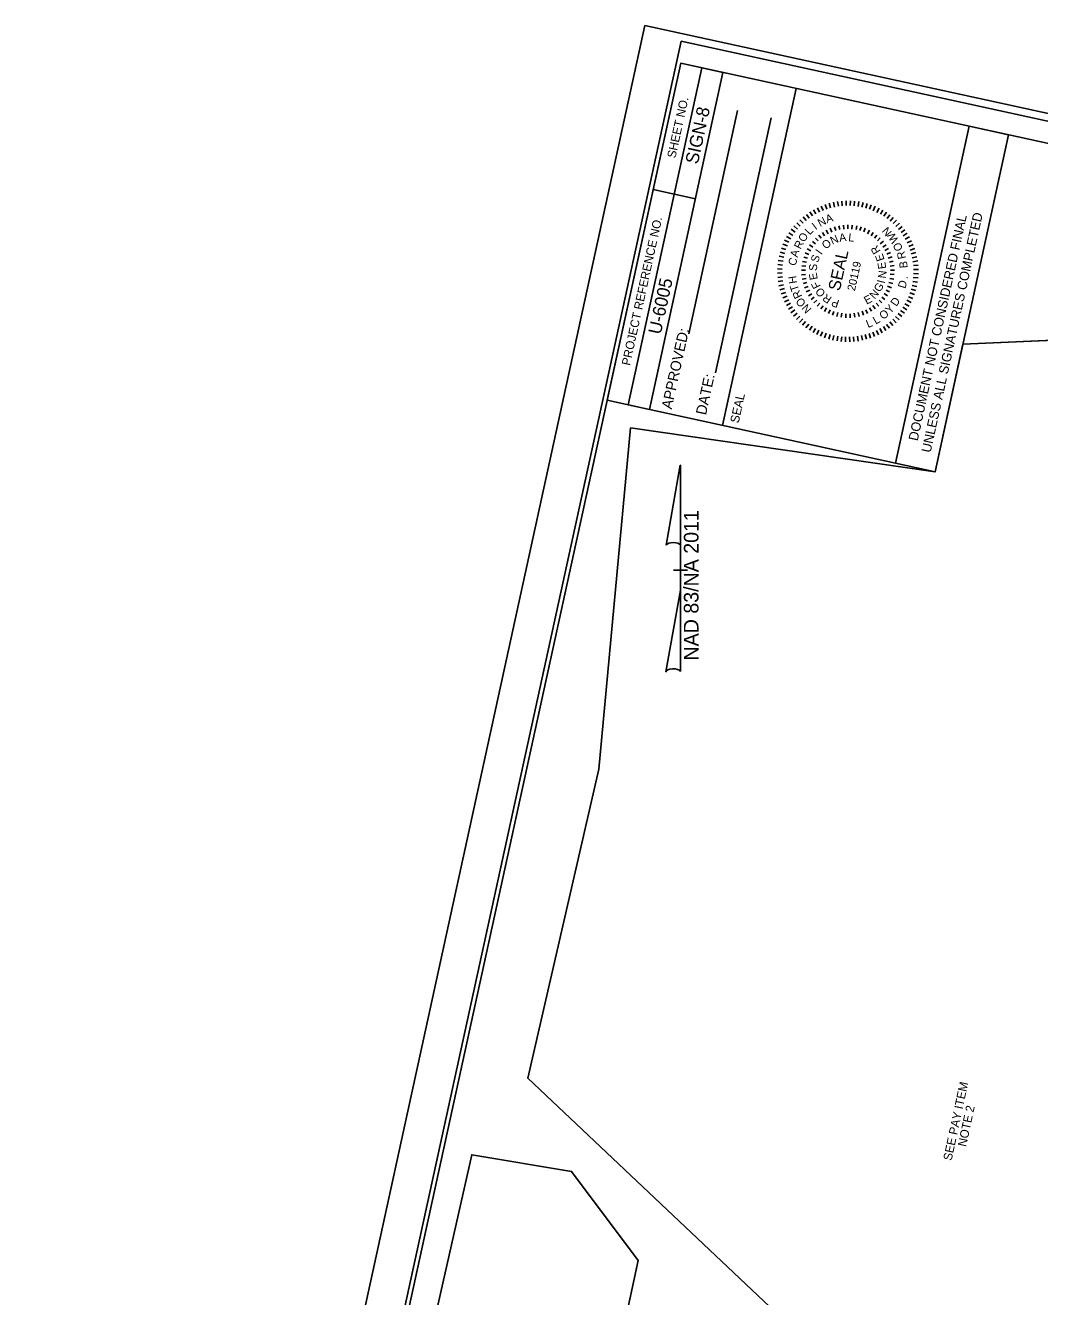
# Model space of a CAD drawing. Extents: x 1615829 to 1617263, y 900664 to 902544.
# Drawn here: x 1615829 to 1616417, y 901807 to 902544 of the extents above; entities that cross this region are included whole.
import ezdxf

# ---------------------------------------------------------------- set-up
doc = ezdxf.new("R2010")
doc.units = 0
for name, color, linetype in [('Default', 7, 'Continuous'), ('Old_Level_19', 7, 'Continuous'), ('Prop Conc 2ft 6in Curb and Gutter', 7, 'Continuous'), ('Prop Conc Drive Radius Type', 7, 'Continuous'), ('Prop Dimension', 7, 'Continuous'), ('Prop Dimension Text', 7, 'Continuous'), ('Prop PHM Concrete Structures Shape', 7, 'Continuous'), ('Prop Shade Medium', 7, 'Continuous'), ('Prop Superelevation  Arrow CELL', 7, 'Continuous'), ('Prop Superelevation Label', 7, 'Continuous'), ('Prop WCC CELL', 7, 'Continuous'), ('Scratch_Level_2', 7, 'Continuous')]:
    doc.layers.add(name, color=color, linetype=linetype)

msp = doc.modelspace()

# ---------------------------------------------------------------- linework, layer by layer
at = {"layer": 'Default'}
for p, q in [((1616283.7, 902435.68), (1616285.2, 902433.33)), ((1616285.81, 902436.95), (1616287.17, 902434.51)), ((1616288.01, 902438.08), (1616289.21, 902435.57)), ((1616290.26, 902439.09), (1616291.32, 902436.51)), ((1616292.57, 902439.95), (1616293.47, 902437.32)), ((1616294.94, 902440.68), (1616295.67, 902437.99)), ((1616297.34, 902441.25), (1616297.91, 902438.53)), ((1616299.77, 902441.69), (1616300.18, 902438.93)), ((1616302.22, 902441.98), (1616302.46, 902439.2)), ((1616304.69, 902442.12), (1616304.75, 902439.33)), ((1616307.15, 902442.11), (1616307.05, 902439.32)), ((1616309.62, 902441.94), (1616309.35, 902439.17)), ((1616312.06, 902441.64), (1616311.63, 902438.89)), ((1616314.49, 902441.18), (1616313.9, 902438.46)), ((1616316.89, 902440.58), (1616316.13, 902437.9)), ((1616319.24, 902439.83), (1616318.32, 902437.21)), ((1616321.55, 902438.95), (1616320.47, 902436.38)), ((1616323.79, 902437.93), (1616322.57, 902435.43)), ((1616325.98, 902436.77), (1616324.6, 902434.35)), ((1616328.08, 902435.49), (1616326.56, 902433.15)), ((1616276.1, 902429.4), (1616278.12, 902427.48)), ((1616277.85, 902431.14), (1616279.75, 902429.1)), ((1616279.71, 902432.77), (1616281.48, 902430.62)), ((1616281.66, 902434.28), (1616283.3, 902432.03)), ((1616303.1, 902428.06), (1616303.32, 902425.75)), ((1616305.69, 902428.2), (1616305.7, 902425.87)), ((1616308.29, 902428.07), (1616308.07, 902425.76)), ((1616330.11, 902434.07), (1616328.45, 902431.83)), ((1616332.05, 902432.54), (1616330.25, 902430.41)), ((1616333.89, 902430.89), (1616331.97, 902428.88)), ((1616335.62, 902429.14), (1616333.59, 902427.24)), ((1616270.22, 902421.49), (1616272.65, 902420.11)), ((1616271.51, 902423.6), (1616273.84, 902422.07)), ((1616272.92, 902425.62), (1616275.16, 902423.97)), ((1616274.45, 902427.56), (1616276.59, 902425.77)), ((1616286.89, 902420.5), (1616288.52, 902418.84)), ((1616288.83, 902422.23), (1616290.29, 902420.42)), ((1616290.94, 902423.76), (1616292.22, 902421.82)), ((1616293.18, 902425.09), (1616294.26, 902423.04)), ((1616295.54, 902426.19), (1616296.42, 902424.04)), ((1616297.99, 902427.06), (1616298.66, 902424.83)), ((1616300.52, 902427.69), (1616300.97, 902425.41)), ((1616310.87, 902427.7), (1616310.43, 902425.42)), ((1616313.4, 902427.08), (1616312.74, 902424.86)), ((1616314.91, 902424.1), (1616315.78, 902426.26)), ((1616318.22, 902425.13), (1616317.15, 902423.07)), ((1616320.47, 902423.81), (1616319.2, 902421.87)), ((1616322.57, 902422.29), (1616321.12, 902420.48)), ((1616324.52, 902420.57), (1616322.91, 902418.9)), ((1616337.25, 902427.29), (1616335.11, 902425.51)), ((1616338.77, 902425.33), (1616336.52, 902423.69)), ((1616340.16, 902423.3), (1616337.82, 902421.8)), ((1616341.43, 902421.18), (1616339, 902419.82)), ((1616267.16, 902414.76), (1616269.79, 902413.84)), ((1616268.04, 902417.06), (1616270.61, 902415.99)), ((1616269.06, 902419.31), (1616271.57, 902418.08)), ((1616282.17, 902414.31), (1616284.2, 902413.18)), ((1616283.54, 902416.52), (1616285.46, 902415.21)), ((1616285.12, 902418.59), (1616286.9, 902417.1)), ((1616326.3, 902418.66), (1616324.53, 902417.16)), ((1616327.88, 902416.6), (1616325.98, 902415.27)), ((1616329.26, 902414.39), (1616327.23, 902413.25)), ((1616342.57, 902418.99), (1616340.06, 902417.78)), ((1616343.57, 902416.73), (1616340.99, 902415.68)), ((1616344.44, 902414.42), (1616341.8, 902413.52)), ((1616265.36, 902407.58), (1616268.11, 902407.15)), ((1616265.81, 902410.01), (1616268.53, 902409.41)), ((1616266.41, 902412.41), (1616269.09, 902411.65)), ((1616279.42, 902407.02), (1616281.69, 902406.53)), ((1616281.69, 902406.53), (1616279.42, 902407.02)), ((1616280.11, 902409.54), (1616282.31, 902408.83)), ((1616281.02, 902411.97), (1616283.15, 902411.05)), ((1616330.42, 902412.06), (1616328.29, 902411.13)), ((1616331.35, 902409.62), (1616329.14, 902408.9)), ((1616332.03, 902407.11), (1616329.76, 902406.61)), ((1616345.16, 902412.06), (1616342.47, 902411.32)), ((1616345.74, 902409.66), (1616343.01, 902409.09)), ((1616346.18, 902407.23), (1616343.42, 902406.82)), ((1616264.88, 902400.2), (1616267.66, 902400.27)), ((1616264.89, 902402.67), (1616267.67, 902402.57)), ((1616265.05, 902405.13), (1616267.82, 902404.87)), ((1616278.81, 902401.86), (1616281.13, 902401.81)), ((1616278.87, 902399.26), (1616281.19, 902399.43)), ((1616278.99, 902404.46), (1616281.29, 902404.18)), ((1616332.48, 902404.54), (1616330.17, 902404.26)), ((1616332.61, 902399.35), (1616330.3, 902399.51)), ((1616332.67, 902401.95), (1616330.35, 902401.89)), ((1616346.46, 902404.78), (1616343.68, 902404.54)), ((1616346.59, 902399.84), (1616343.81, 902399.94)), ((1616346.6, 902402.31), (1616343.82, 902402.24)), ((1616265.01, 902397.73), (1616267.79, 902397.97)), ((1616265.3, 902395.28), (1616268.06, 902395.69)), ((1616265.74, 902392.85), (1616268.46, 902393.42)), ((1616266.31, 902390.45), (1616269, 902391.19)), ((1616279.19, 902396.68), (1616281.48, 902397.07)), ((1616279.76, 902394.13), (1616281.99, 902394.75)), ((1616280.56, 902391.66), (1616282.74, 902392.49)), ((1616330.94, 902391.75), (1616328.77, 902392.56)), ((1616331.75, 902394.22), (1616329.5, 902394.82)), ((1616332.3, 902396.76), (1616330.01, 902397.15)), ((1616345.66, 902392.5), (1616342.94, 902393.1)), ((1616346.12, 902394.93), (1616343.37, 902395.36)), ((1616346.43, 902397.38), (1616343.66, 902397.64)), ((1616267.04, 902388.09), (1616269.68, 902388.99)), ((1616267.91, 902385.78), (1616270.48, 902386.83)), ((1616268.91, 902383.53), (1616271.42, 902384.73)), ((1616281.61, 902389.27), (1616283.69, 902390.31)), ((1616282.88, 902387), (1616284.85, 902388.23)), ((1616284.36, 902384.86), (1616286.2, 902386.27)), ((1616286.04, 902382.87), (1616287.74, 902384.46)), ((1616325.49, 902382.94), (1616323.79, 902384.52)), ((1616327.17, 902384.94), (1616325.32, 902386.34)), ((1616328.65, 902387.08), (1616326.67, 902388.3)), ((1616327.82, 902390.37), (1616329.9, 902389.34)), ((1616342.41, 902383.2), (1616339.91, 902384.43)), ((1616343.43, 902385.45), (1616340.87, 902386.52)), ((1616344.32, 902387.75), (1616341.69, 902388.67)), ((1616345.06, 902390.11), (1616342.38, 902390.86)), ((1616270.05, 902381.33), (1616272.48, 902382.69)), ((1616271.32, 902379.21), (1616273.66, 902380.72)), ((1616272.71, 902377.18), (1616274.96, 902378.82)), ((1616274.23, 902375.22), (1616276.37, 902377)), ((1616287.9, 902381.06), (1616289.45, 902382.8)), ((1616289.94, 902379.43), (1616291.3, 902381.31)), ((1616292.12, 902378.01), (1616293.29, 902380.02)), ((1616294.43, 902376.8), (1616295.4, 902378.91)), ((1616296.84, 902375.83), (1616297.6, 902378.02)), ((1616299.33, 902375.09), (1616299.89, 902377.34)), ((1616301.89, 902374.59), (1616302.22, 902376.89)), ((1616304.48, 902374.35), (1616304.59, 902376.66)), ((1616307.09, 902374.35), (1616306.97, 902376.66)), ((1616309.68, 902374.6), (1616309.34, 902376.9)), ((1616312.23, 902375.11), (1616311.67, 902377.36)), ((1616314.72, 902375.86), (1616313.95, 902378.05)), ((1616317.13, 902376.84), (1616316.15, 902378.95)), ((1616319.43, 902378.06), (1616318.26, 902380.05)), ((1616321.61, 902379.48), (1616320.24, 902381.36)), ((1616323.63, 902381.12), (1616322.09, 902382.85)), ((1616337.03, 902374.95), (1616334.89, 902376.74)), ((1616338.55, 902376.89), (1616336.32, 902378.55)), ((1616339.97, 902378.91), (1616337.63, 902380.44)), ((1616341.26, 902381.02), (1616338.83, 902382.4)), ((1616275.85, 902373.37), (1616277.89, 902375.27)), ((1616277.59, 902371.62), (1616279.51, 902373.63)), ((1616279.43, 902369.97), (1616281.23, 902372.1)), ((1616281.37, 902368.44), (1616283.03, 902370.68)), ((1616283.39, 902367.03), (1616284.92, 902369.36)), ((1616327.78, 902366.83), (1616326.28, 902369.18)), ((1616329.82, 902368.23), (1616328.18, 902370.48)), ((1616331.77, 902369.74), (1616330, 902371.89)), ((1616333.62, 902371.37), (1616331.73, 902373.41)), ((1616335.38, 902373.11), (1616333.36, 902375.03)), ((1616285.5, 902365.74), (1616286.88, 902368.16)), ((1616287.69, 902364.58), (1616288.91, 902367.08)), ((1616289.93, 902363.56), (1616291.01, 902366.13)), ((1616292.24, 902362.68), (1616293.15, 902365.3)), ((1616294.59, 902361.93), (1616295.35, 902364.61)), ((1616296.98, 902361.33), (1616297.58, 902364.05)), ((1616299.41, 902360.87), (1616299.84, 902363.62)), ((1616301.86, 902360.57), (1616302.13, 902363.34)), ((1616304.32, 902360.4), (1616304.42, 902363.19)), ((1616306.79, 902360.39), (1616306.72, 902363.18)), ((1616309.26, 902360.53), (1616309.02, 902363.31)), ((1616311.71, 902360.82), (1616311.3, 902363.58)), ((1616314.14, 902361.26), (1616313.57, 902363.98)), ((1616316.54, 902361.83), (1616315.81, 902364.52)), ((1616318.9, 902362.56), (1616318, 902365.19)), ((1616321.22, 902363.42), (1616320.16, 902366)), ((1616323.47, 902364.43), (1616322.26, 902366.94)), ((1616325.66, 902365.57), (1616324.3, 902368))]:
    msp.add_line(p, q, dxfattribs=at)
at = {"layer": 'Prop Conc 2ft 6in Curb and Gutter'}
for p, q in [((1616200.34, 902242.5), (1616208.54, 902288.85)), ((1616208.59, 902288.85), (1616208.54, 902288.85)), ((1616208.59, 902288.85), (1616208.54, 902288.85)), ((1616208.59, 902288.85), (1616208.59, 902241.05)), ((1616208.59, 902216.25), (1616208.59, 902242.45)), ((1616208.59, 902241.05), (1616208.59, 902242.4)), ((1616204.59, 902227.85), (1616204.54, 902227.85)), ((1616208.14, 902227.85), (1616204.59, 902227.85)), ((1616204.64, 902227.85), (1616212.64, 902227.85)), ((1616208.59, 902216.25), (1616200.24, 902169)), ((1616208.64, 902169.2), (1616208.59, 902216.25))]:
    msp.add_line(p, q, dxfattribs=at)
for centre, start_param, end_param in [((1616204.47, 902242), 0.216388, 2.908219), ((1616204.47, 902168.83), 0.201328, 3.141593)]:
    msp.add_ellipse(centre, major_axis=(4.23, -0.03), ratio=0.461098, start_param=start_param, end_param=end_param, dxfattribs=at)
at = {"layer": 'Prop Conc Drive Radius Type'}
msp.add_lwpolyline([(1616850.42, 902379.94), (1617227.49, 902296.2), (1617121.36, 901790.43), (1617088.18, 901641.75), (1617042.44, 901522.26), (1617032.35, 901430.63), (1617021.35, 901334.38), (1616928.77, 900896.77), (1615902.83, 901120.28), (1615974.27, 901386.7), (1616087.67, 901888.92), (1616145.49, 901879.24), (1616184.12, 901827.49), (1616138.37, 901614.97), (1616150.59, 901618.07), (1616181.32, 901620.66), (1616299.19, 901764.2), (1616120.07, 901933.32), (1616161.35, 902112.51), (1616179.69, 902310.42), (1616356.27, 902284.95), (1616372.44, 902359.01)], close=True, dxfattribs=at)
at = {"layer": 'Prop Dimension'}
msp.add_lwpolyline([(1616333.32, 902289.96), (1616375.98, 902485.4), (1616398.93, 902480.39), (1616356.27, 902284.95)], close=True, dxfattribs=at)
at = {"layer": 'Prop Dimension Text'}
msp.add_line((1616372.44, 902359.01), (1616856.51, 902380.51), dxfattribs=at)
at = {"layer": 'Prop PHM Concrete Structures Shape'}
for p, q in [((1616178.38, 902323.78), (1616221.05, 902519.22)), ((1616190.6, 902321.11), (1616233.26, 902516.56)), ((1616190.6, 902321.11), (1616233.26, 902516.56)), ((1616192.84, 902448.61), (1616217.27, 902443.28))]:
    msp.add_line(p, q, dxfattribs=at)
for points in [[(1616208.79, 902521.9), (1615888.89, 901056.41), (1616914.73, 900832.48), (1617234.63, 902297.97)], [(1616166.12, 902326.45), (1616208.79, 902521.9), (1616233.26, 902516.56), (1616190.6, 902321.11)]]:
    msp.add_lwpolyline(points, close=True, dxfattribs=at)
at = {"layer": 'Prop Shade Medium'}
msp.add_lwpolyline([(1616187.99, 902543.84), (1615828.85, 900898.58), (1616903.54, 900663.99), (1617262.68, 902309.25)], close=True, dxfattribs=at)
at = {"layer": 'Prop Superelevation  Arrow CELL'}
for p, q in [((1616233.02, 902311.85), (1616275.68, 902507.3)), ((1616375.98, 902485.4), (1616333.32, 902289.96)), ((1616224.48, 902313.71), (1616178.38, 902323.78)), ((1616333.32, 902289.96), (1616224.48, 902313.71))]:
    msp.add_line(p, q, dxfattribs=at)
at = {"layer": 'Prop WCC CELL'}
for p, q in [((1616213.43, 902364.94), (1616241.71, 902494.5)), ((1616228.89, 902342.44), (1616261.16, 902490.26))]:
    msp.add_line(p, q, dxfattribs=at)
at = {"layer": 'Scratch_Level_2'}
msp.add_lwpolyline([(1616208.96, 902534.66), (1615853.55, 900906.5), (1616884.38, 900681.48), (1617239.79, 902309.64)], close=True, dxfattribs=at)

# ---------------------------------------------------------------- texts
at = {"layer": 'Default'}
for s, height, rotation, p in [('I', 4.64, 37.2123, (1616287.03, 902425.04)), ('N', 4.64, 27.91784, (1616289.67, 902426.85)), ('A', 4.64, 18.15031, (1616293.67, 902429.11)), ('O', 4.64, 59.92405, (1616280.57, 902417.8)), ('L', 4.64, 46.78777, (1616283.6, 902421.97)), ('N', 4.64, 24.09635, (1616296.7, 902416.6)), ('A', 4.64, 8.8001, (1616300.96, 902418.27)), ('L', 4.64, 353.50386, (1616305.77, 902418.76)), ('N', 4.64, 129.84026, (1616331.57, 902424.01)), ('W', 4.64, 120.95763, (1616335.3, 902419.21)), ('R', 4.64, 62.98087, (1616278.31, 902413.69)), ('I', 4.64, 54.68884, (1616290.34, 902410.51)), ('O', 4.64, 39.39259, (1616292.9, 902413.78)), ('R', 4.64, 122.1981, (1616324.86, 902412.97)), ('O', 4.64, 112.07501, (1616337.73, 902414.01)), ('C', 4.64, 74.99017, (1616275.41, 902404.1)), ('A', 4.64, 74.99017, (1616276.58, 902409.04)), ('S', 4.64, 69.98509, (1616288.3, 902405.9)), ('SEAL', 6.965, 77.63321, (1616301.02, 902389.51)), ('20119', 4.64, 77.63321, (1616309.77, 902389.54)), ('E', 4.64, 108.42701, (1616327.07, 902407.96)), ('E', 4.64, 98.44113, (1616327.99, 902402.89)), ('R', 4.64, 103.25239, (1616339.45, 902408.91)), ('B', 4.64, 94.24983, (1616340.36, 902403.22)), ('H', 4.64, 98.70086, (1616276.34, 902394.45)), ('E', 4.64, 100.57758, (1616288.31, 902396.7)), ('S', 4.64, 85.28133, (1616287.69, 902401.29)), ('N', 4.64, 83.04906, (1616327.74, 902396.93)), ('T', 4.64, 108.13281, (1616277.52, 902390.37)), ('F', 4.64, 115.87382, (1616290.08, 902392.51)), ('O', 4.64, 131.17007, (1616293.07, 902388.69)), ('G', 4.64, 57.32461, (1616324.28, 902388.8)), ('I', 4.64, 75.4194, (1616326.92, 902393.88)), ('D', 4.64, 73.72316, (1616339, 902390.95)), ('.', 4.64, 81.46551, (1616340.29, 902396.66)), ('R', 4.64, 116.29377, (1616279.38, 902386.76)), ('O', 4.64, 129.35051, (1616281.72, 902382.81)), ('R', 4.64, 146.46631, (1616296.75, 902386.01)), ('P', 4.64, 161.76256, (1616301.09, 902384.34)), ('E', 4.64, 27.7033, (1616316.57, 902381.86)), ('N', 4.64, 48.55837, (1616321.18, 902384.83)), ('D', 4.64, 55.92785, (1616333.83, 902380.53)), ('N', 4.64, 131.30994, (1616284.97, 902379.37)), ('O', 4.64, 38.28279, (1616326.17, 902372.95)), ('Y', 4.64, 46.95537, (1616330.23, 902376.38)), ('L', 4.64, 21.56822, (1616317.33, 902368.33)), ('L', 4.64, 29.64004, (1616321.84, 902370.29)), ('SEE PAY ITEM', 5, 77.92233, (1616365.83, 901885.2)), ('NOTE 2', 5, 77.92233, (1616374.26, 901893.28))]:
    msp.add_text(s, height=height, rotation=rotation, dxfattribs=at).set_placement(p)
at = {"layer": 'Old_Level_19'}
for s, p in [('SIGN-8', (1616218.7, 902462.99)), ('U-6005', (1616197.2, 902364.24))]:
    msp.add_text(s, height=7.5, rotation=77.68623, dxfattribs=at).set_placement(p)
at = {"layer": 'Prop Conc 2ft 6in Curb and Gutter'}
msp.add_text('NAD 83/NA 2011', height=8.5, rotation=90, dxfattribs=at).set_placement((1616219.11, 902175.54))
at = {"layer": 'Prop Dimension'}
for s, p in [('DOCUMENT NOT CONSIDERED FINAL', (1616346.16, 902302.58)), ('UNLESS ALL SIGNATURES COMPLETED', (1616353.67, 902295.75))]:
    msp.add_text(s, height=5.4984, rotation=77.68623, dxfattribs=at).set_placement(p)
at = {"layer": 'Prop PHM Concrete Structures Shape'}
for s, height, p in [('SHEET NO.', 5, (1616205.72, 902466.58)), ('PROJECT REFERENCE NO.', 5.0001, (1616179.36, 902346.29))]:
    msp.add_text(s, height=height, rotation=77.68623, dxfattribs=at).set_placement(p)
at = {"layer": 'Prop Superelevation Label'}
for s, p in [('APPROVED:', (1616203.55, 902320.93)), ('DATE:', (1616223.42, 902317.53))]:
    msp.add_text(s, height=6.11, rotation=77.68116, dxfattribs=at).set_placement(p)
at = {"layer": 'Prop WCC CELL'}
msp.add_text('SEAL', height=5.094, rotation=77.68116, dxfattribs=at).set_placement((1616242.37, 902312.91))

doc.saveas('drawing.dxf')
